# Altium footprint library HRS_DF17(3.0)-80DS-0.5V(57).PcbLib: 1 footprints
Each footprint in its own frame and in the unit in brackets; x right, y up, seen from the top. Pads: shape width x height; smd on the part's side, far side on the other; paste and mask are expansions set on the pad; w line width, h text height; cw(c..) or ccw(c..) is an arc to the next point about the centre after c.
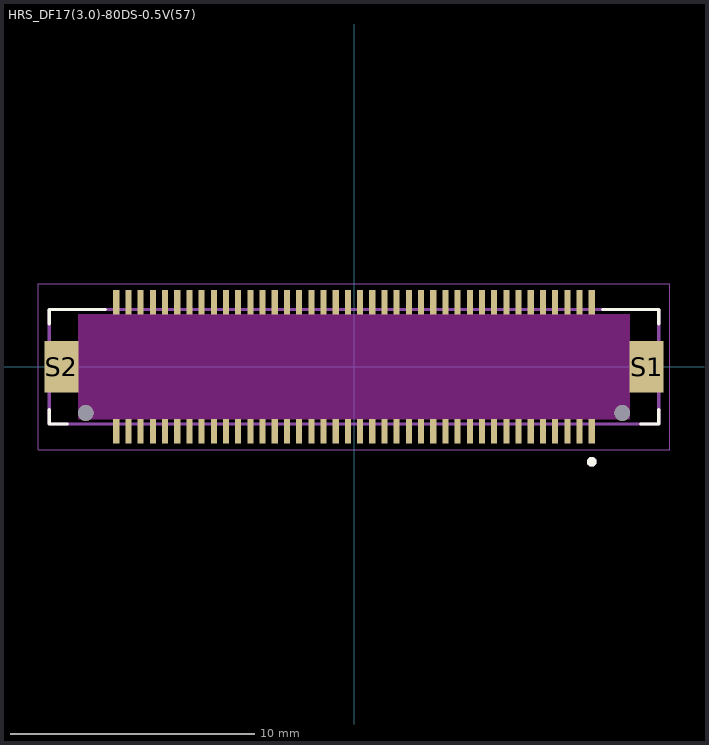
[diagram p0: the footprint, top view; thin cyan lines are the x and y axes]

## HRS_DF17(3.0)-80DS-0.5V(57) [mm]
pads (84):
  rect 0.25x1 smd paste+0 mask+0.102: 1(9.75,-2.65) 2(9.75,2.65) 3(9.25,-2.65) 4(9.25,2.65) 5(8.75,-2.65) 6(8.75,2.65) 7(8.25,-2.65) 8(8.25,2.65) 9(7.75,-2.65) 10(7.75,2.65) 11(7.25,-2.65) 12(7.25,2.65) 13(6.75,-2.65) 14(6.75,2.65) 15(6.25,-2.65) 16(6.25,2.65) 17(5.75,-2.65) 18(5.75,2.65) 19(5.25,-2.65) 20(5.25,2.65) 21(4.75,-2.65) 22(4.75,2.65) 23(4.25,-2.65) 24(4.25,2.65) 25(3.75,-2.65) 26(3.75,2.65) 27(3.25,-2.65) 28(3.25,2.65) 29(2.75,-2.65) 30(2.75,2.65) 31(2.25,-2.65) 32(2.25,2.65) 33(1.75,-2.65) 34(1.75,2.65) 35(1.25,-2.65) 36(1.25,2.65) 37(0.75,-2.65) 38(0.75,2.65) 39(0.25,-2.65) 40(0.25,2.65) 41(-0.25,-2.65) 42(-0.25,2.65) 43(-0.75,-2.65) 44(-0.75,2.65) 45(-1.25,-2.65) 46(-1.25,2.65) 47(-1.75,-2.65) 48(-1.75,2.65) 49(-2.25,-2.65) 50(-2.25,2.65) 51(-2.75,-2.65) 52(-2.75,2.65) 53(-3.25,-2.65) 54(-3.25,2.65) 55(-3.75,-2.65) 56(-3.75,2.65) 57(-4.25,-2.65) 58(-4.25,2.65) 59(-4.75,-2.65) 60(-4.75,2.65) 61(-5.25,-2.65) 62(-5.25,2.65) 63(-5.75,-2.65) 64(-5.75,2.65) 65(-6.25,-2.65) 66(-6.25,2.65) 67(-6.75,-2.65) 68(-6.75,2.65) 69(-7.25,-2.65) 70(-7.25,2.65) 71(-7.75,-2.65) 72(-7.75,2.65) 73(-8.25,-2.65) 74(-8.25,2.65) 75(-8.75,-2.65) 76(-8.75,2.65) 77(-9.25,-2.65) 78(-9.25,2.65) 79(-9.75,-2.65) 80(-9.75,2.65)
  rect 1.4x2.1 smd paste+0 mask+0.102: S1(12,0) S2(-12,0)
  round 0.65 hole 0.65 unplated mask+0: ""(-11,-1.9) ""(11,-1.9)
Top Overlay:
  circle w0.2: c9.75,-3.9 r0.1
  lines w0.127: -12.5,-1.75 -12.5,-2.35 -11.75,-2.35 ; -12.5,1.75 -12.5,2.35 -10.195,2.35 ; 10.195,2.35 12.5,2.35 12.5,1.75 ; 11.75,-2.35 12.5,-2.35 12.5,-1.75
Keep-Out Layer:
  region: 11.3,-2.15 -11.3,-2.15 -11.3,2.15 11.3,2.15
Assembly Top:
  circle w0.2: c9.75,-3.9 r0.1
  lines w0.127: -12.5,-2.35 12.5,-2.35 12.5,2.35 -12.5,2.35 -12.5,-2.35
Courtyard Top:
  lines w0.05: -12.95,-3.4 12.95,-3.4 12.95,3.4 -12.95,3.4 -12.95,-3.4
3D body "step_temp.STEP": height 3.5, standoff -0.6, extent -12.493,-2.85 12.507,2.85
